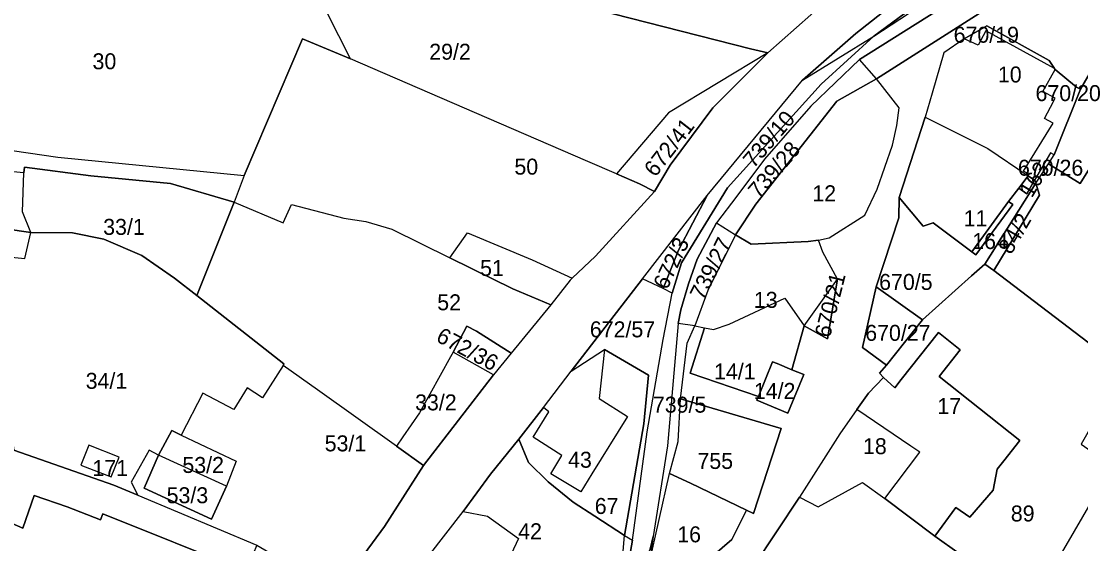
# Model space of a CAD drawing. Extents: x -629983 to -626385, y -1072828 to -1067897.
# Drawn here: x -627471.3 to -627272.2, y -1070358.3 to -1070260.1 of the extents above; entities that cross this region are included whole.
import ezdxf

# ---------------------------------------------------------------- set-up
doc = ezdxf.new("R2010")
doc.units = 0
doc.layers.add('Parcela nároku', color=7, linetype='Continuous')
doc.layers.add('Parcelní číslo', color=7, linetype='Continuous')

msp = doc.modelspace()

# ---------------------------------------------------------------- linework, layer by layer
at = {"layer": 'Parcela nároku'}
for points in [[(-627274.33, -1070229.94), (-627293.26, -1070245.57), (-627314.49, -1070262.38), (-627324.47, -1070271.16), (-627311.08, -1070262.87), (-627302.99, -1070256.91), (-627285.94, -1070243.76), (-627262.58, -1070228.21), (-627241.08, -1070214.74), (-627233.73, -1070210.98), (-627219.25, -1070207.1), (-627223.95, -1070202.72), (-627229.52, -1070202.24), (-627256.58, -1070217.73)], [(-627281.4, -1070246.83), (-627235.72, -1070217.21), (-627221.49, -1070213.01), (-627179.8, -1070206.02), (-627218.8, -1070213.83), (-627232.77, -1070222.84), (-627237.4, -1070226.24), (-627249.09, -1070231.35), (-627251.32, -1070233.14), (-627310.6, -1070270.86), (-627313.75, -1070267.23)], [(-627285.94, -1070243.76), (-627302.99, -1070256.91), (-627311.08, -1070262.87), (-627283.38, -1070244.72), (-627253.74, -1070227.22), (-627230.57, -1070214.05), (-627219.25, -1070207.1), (-627233.73, -1070210.98), (-627241.08, -1070214.74), (-627262.58, -1070228.21)], [(-627369.9, -1070256.15), (-627334.23, -1070265.22), (-627330.99, -1070266.01), (-627349.67, -1070277.25), (-627359.4, -1070288.74), (-627364.81, -1070286.4), (-627383.81, -1070278.2), (-627409.42, -1070267.15), (-627420.23, -1070245.71), (-627451.48, -1070240.87), (-627477.24, -1070236.31), (-627454.65, -1070210.58), (-627405.34, -1070220.98), (-627383.62, -1070245.45), (-627385.11, -1070252.28), (-627374.12, -1070255.08)], [(-627327.06, -1070239.59), (-627318.56, -1070244.65), (-627312.14, -1070249.25), (-627330.99, -1070266.01), (-627334.23, -1070265.22), (-627369.9, -1070256.15), (-627374.12, -1070255.08), (-627385.11, -1070252.28), (-627383.62, -1070245.45), (-627405.34, -1070220.98), (-627389.65, -1070224.29), (-627369.93, -1070230.55), (-627368.92, -1070227.99), (-627367.23, -1070223.22), (-627357.1, -1070227.42)], [(-627477.24, -1070236.31), (-627484.54, -1070251.9), (-627500.04, -1070281.83), (-627475.57, -1070284), (-627464.35, -1070285.62), (-627429.37, -1070289.04), (-627418.41, -1070263.38), (-627409.42, -1070267.15), (-627420.23, -1070245.71), (-627451.48, -1070240.87)], [(-627294.09, -1070263.34), (-627289.87, -1070260.94), (-627278.17, -1070267.43), (-627277.17, -1070268.92), (-627290.07, -1070261.89), (-627291.5, -1070264.57)], [(-627245.28, -1070273.22), (-627237.36, -1070278.17), (-627245.44, -1070292.1), (-627254.18, -1070287.03), (-627269.14, -1070285.43), (-627272.3, -1070290.53), (-627278.26, -1070286.84), (-627277.22, -1070285.2), (-627272.23, -1070272.86), (-627269.77, -1070268.48), (-627265.69, -1070260.15), (-627259.39, -1070263.83), (-627249.14, -1070270.65)], [(-627359.4, -1070288.74), (-627364.81, -1070286.4), (-627383.81, -1070278.2), (-627409.42, -1070267.15), (-627418.41, -1070263.38), (-627429.37, -1070289.04), (-627431.24, -1070294.08), (-627422.01, -1070297.98), (-627420.45, -1070294.52), (-627410.65, -1070297.05), (-627406.5, -1070297.67), (-627401.6, -1070299.12), (-627390.72, -1070304.51), (-627387.4, -1070299.82), (-627375.27, -1070304.93), (-627367.77, -1070308.37), (-627363.34, -1070304.23), (-627352.3, -1070292.06), (-627355.08, -1070290.6)], [(-627342.39, -1070292.8), (-627324.47, -1070271.16), (-627311.08, -1070262.87), (-627321, -1070271.87), (-627338.56, -1070291.39), (-627347.24, -1070305.44), (-627348.95, -1070311.14), (-627350.65, -1070310.32), (-627347.8, -1070303.06)], [(-627277.01, -1070274.54), (-627279.33, -1070273.25), (-627277.04, -1070269.12), (-627277.17, -1070268.92), (-627290.07, -1070261.89), (-627291.5, -1070264.57), (-627294.09, -1070263.34), (-627297.92, -1070265.98), (-627300.1, -1070273.55), (-627301.44, -1070278.09), (-627289.65, -1070284), (-627282.12, -1070289.1), (-627281.95, -1070288.79), (-627282.97, -1070288.21), (-627277.42, -1070279.24), (-627279.02, -1070278.33), (-627277.35, -1070275.17)], [(-627330.99, -1070266.01), (-627349.67, -1070277.25), (-627359.4, -1070288.74), (-627355.08, -1070290.6), (-627352.3, -1070292.06), (-627349.34, -1070287.13), (-627341.32, -1070276.32)], [(-627336.83, -1070292.94), (-627340.61, -1070297.95), (-627337.09, -1070300.21), (-627333.27, -1070294.46), (-627318.04, -1070275.09), (-627310.6, -1070270.86), (-627313.75, -1070267.23), (-627322.9, -1070276), (-627331.6, -1070286)], [(-627279.33, -1070273.25), (-627277.04, -1070269.12), (-627273, -1070272.48), (-627272.23, -1070272.86), (-627277.22, -1070285.2), (-627277.92, -1070284.77), (-627280.9, -1070289.93), (-627282.12, -1070289.1), (-627281.95, -1070288.79), (-627282.97, -1070288.21), (-627277.42, -1070279.24), (-627279.02, -1070278.33), (-627277.35, -1070275.17), (-627277.01, -1070274.54)], [(-627333.27, -1070294.46), (-627337.09, -1070300.21), (-627334.11, -1070301.99), (-627323.44, -1070301.49), (-627321.48, -1070301.2), (-627319.48, -1070300.75), (-627312.8, -1070296.52), (-627310.43, -1070291.6), (-627307.55, -1070283.36), (-627306.75, -1070279.66), (-627306.34, -1070276.31), (-627310.6, -1070270.86), (-627318.04, -1070275.09)], [(-627289.65, -1070284), (-627282.12, -1070289.1), (-627283.87, -1070291.42), (-627285.76, -1070293.94), (-627292.7, -1070303.39), (-627299.96, -1070297.97), (-627301.82, -1070298.6), (-627306.32, -1070293.18), (-627301.44, -1070278.09)], [(-627464.35, -1070285.62), (-627429.37, -1070289.04), (-627431.24, -1070294.08), (-627443.18, -1070290.54), (-627458.17, -1070289.11), (-627470.63, -1070287.47), (-627470.75, -1070288.53), (-627501.98, -1070285.58), (-627500.04, -1070281.83), (-627475.57, -1070284)], [(-627277.22, -1070285.2), (-627277.92, -1070284.77), (-627280.9, -1070289.93), (-627280.73, -1070290.16), (-627280.63, -1070290.51), (-627278.26, -1070286.84)], [(-627479.02, -1070297.25), (-627479.04, -1070298.42), (-627469.42, -1070299.74), (-627471.01, -1070295.88), (-627470.75, -1070288.53), (-627501.98, -1070285.58), (-627506.48, -1070294.32), (-627490.24, -1070295.72)], [(-627269.14, -1070285.43), (-627254.18, -1070287.03), (-627245.44, -1070292.1), (-627266.97, -1070320.91), (-627268.23, -1070322.38), (-627288.54, -1070306.92), (-627279.99, -1070292.78), (-627280.63, -1070290.51), (-627278.26, -1070286.84), (-627272.3, -1070290.53)], [(-627458.17, -1070289.11), (-627443.18, -1070290.54), (-627431.24, -1070294.08), (-627438.26, -1070311.63), (-627442.44, -1070308.35), (-627448.6, -1070304.07), (-627455.76, -1070301), (-627461.62, -1070299.82), (-627469.42, -1070299.74), (-627471.01, -1070295.88), (-627470.75, -1070288.53), (-627470.63, -1070287.47)], [(-627282.12, -1070289.1), (-627280.9, -1070289.93), (-627282.36, -1070292.48), (-627283.87, -1070291.42)], [(-627301.82, -1070298.6), (-627299.96, -1070297.97), (-627292.7, -1070303.39), (-627291.94, -1070303.96), (-627284.99, -1070294.5), (-627285.76, -1070293.94), (-627283.87, -1070291.42), (-627282.36, -1070292.48), (-627280.9, -1070289.93), (-627280.73, -1070290.16), (-627280.63, -1070290.51), (-627290.23, -1070305.72), (-627292.73, -1070307.89), (-627301.97, -1070316.17), (-627310.63, -1070309.97), (-627306.4, -1070297.04), (-627306.32, -1070293.18)], [(-627280.63, -1070290.51), (-627279.99, -1070292.78), (-627288.54, -1070306.92), (-627290.23, -1070305.72)], [(-627354.53, -1070308.48), (-627342.39, -1070292.8), (-627347.8, -1070303.06), (-627350.65, -1070310.32)], [(-627378.87, -1070310.38), (-627371.73, -1070313.39), (-627379.18, -1070322.46), (-627385.75, -1070318.34), (-627387.51, -1070317.39), (-627390.09, -1070322.26), (-627390.58, -1070323.13), (-627396.45, -1070333.65), (-627399.58, -1070338.17), (-627400.78, -1070339.91), (-627415.62, -1070329.36), (-627422.06, -1070324.78), (-627421.91, -1070324.46), (-627438.26, -1070311.63), (-627431.24, -1070294.08), (-627422.01, -1070297.98), (-627420.45, -1070294.52), (-627410.65, -1070297.05), (-627406.5, -1070297.67), (-627401.6, -1070299.12), (-627390.72, -1070304.51)], [(-627285.76, -1070293.94), (-627284.99, -1070294.5), (-627291.94, -1070303.96), (-627292.7, -1070303.39)], [(-627469.42, -1070299.74), (-627479.04, -1070298.42), (-627493.23, -1070296.53), (-627507.13, -1070295.59), (-627509.97, -1070301.16), (-627510.28, -1070301.76), (-627502.57, -1070305.47), (-627493.05, -1070303.61), (-627489.75, -1070302.95), (-627478.71, -1070303.86), (-627478.14, -1070303.92), (-627470.55, -1070304.67)], [(-627340.61, -1070297.95), (-627337.09, -1070300.21), (-627342.27, -1070310.69), (-627344.74, -1070317.31), (-627347.86, -1070316.85), (-627347.33, -1070314.29), (-627345.92, -1070309.44), (-627344.25, -1070304.76)], [(-627461.62, -1070299.82), (-627455.76, -1070301), (-627448.6, -1070304.07), (-627442.44, -1070308.35), (-627438.26, -1070311.63), (-627421.91, -1070324.46), (-627422.06, -1070324.78), (-627425.91, -1070330.87), (-627428.78, -1070328.99), (-627431.33, -1070333.05), (-627437.16, -1070329.94), (-627441.2, -1070337.83), (-627442.96, -1070336.99), (-627445.44, -1070341.59), (-627447.23, -1070340.65), (-627450.6, -1070346.67), (-627449.35, -1070349.16), (-627453.84, -1070347.28), (-627472.61, -1070340.67), (-627478.14, -1070303.92), (-627470.55, -1070304.67), (-627469.42, -1070299.74)], [(-627375.27, -1070304.93), (-627367.77, -1070308.37), (-627368.12, -1070308.7), (-627371.73, -1070313.39), (-627378.87, -1070310.38), (-627390.72, -1070304.51), (-627387.4, -1070299.82)], [(-627337.09, -1070300.21), (-627342.27, -1070310.69), (-627344.74, -1070317.31), (-627342.9, -1070317.68), (-627341.18, -1070317.97), (-627338.28, -1070317.01), (-627327.83, -1070312.1), (-627324.2, -1070317.33), (-627317.89, -1070308.52), (-627320.64, -1070303.47), (-627321.48, -1070301.2), (-627323.44, -1070301.49), (-627334.11, -1070301.99)], [(-627478.14, -1070303.92), (-627472.61, -1070340.67), (-627453.84, -1070347.28), (-627449.35, -1070349.16), (-627426.96, -1070358.52), (-627429.07, -1070363.41), (-627455.93, -1070352.67), (-627456.37, -1070353.79), (-627462.61, -1070351.34), (-627468.81, -1070349.21), (-627470.94, -1070355.34), (-627478.59, -1070352.03), (-627499.33, -1070342.21), (-627492.09, -1070303.67), (-627478.71, -1070304.58), (-627478.71, -1070303.86)], [(-627348.95, -1070311.14), (-627350.65, -1070310.32), (-627354.53, -1070308.48), (-627367.96, -1070325.83), (-627361.7, -1070321.78), (-627353.44, -1070326.59), (-627354.29, -1070335.76), (-627357.89, -1070356.74), (-627356.41, -1070357.6), (-627353.65, -1070337.23), (-627350.65, -1070319.87)], [(-627324.2, -1070317.33), (-627317.89, -1070308.52), (-627319.78, -1070319.75)], [(-627313.2, -1070321.39), (-627310.63, -1070309.97), (-627301.97, -1070316.17), (-627308.72, -1070324.72)], [(-627338.28, -1070317.01), (-627327.83, -1070312.1), (-627324.2, -1070317.33), (-627326.48, -1070325.55), (-627329.26, -1070324.4), (-627330.11, -1070324.05), (-627332.78, -1070330.59), (-627345.58, -1070326.23), (-627342.9, -1070317.68), (-627341.18, -1070317.97)], [(-627347.86, -1070316.85), (-627349.85, -1070339.86), (-627352.52, -1070356.91), (-627353.37, -1070362.37), (-627349.44, -1070345.07), (-627347.83, -1070339.08), (-627347.37, -1070331.02), (-627346.17, -1070320.59), (-627344.74, -1070317.31)], [(-627385.75, -1070318.34), (-627379.18, -1070322.46), (-627382.5, -1070326.5), (-627390.09, -1070322.26), (-627387.51, -1070317.39)], [(-627305.92, -1070327.38), (-627298.95, -1070318.59), (-627294.84, -1070321.85), (-627298.81, -1070326.86), (-627283.65, -1070338.87), (-627286.65, -1070342.66), (-627287.89, -1070344.23), (-627288.67, -1070348.17), (-627293.06, -1070353.29), (-627295.67, -1070351.47), (-627299.63, -1070356.83), (-627309, -1070349.79), (-627302.45, -1070341.03), (-627304.11, -1070339.91), (-627314.26, -1070333.05), (-627312.06, -1070329.96), (-627309.24, -1070327.02), (-627307.16, -1070328.95)], [(-627396.45, -1070333.65), (-627399.58, -1070338.17), (-627400.78, -1070339.91), (-627395.65, -1070343.56), (-627382.5, -1070326.5), (-627390.09, -1070322.26), (-627390.58, -1070323.13)], [(-627366.14, -1070348.54), (-627371.76, -1070345.13), (-627369.68, -1070341.71), (-627375.1, -1070338.24), (-627372.12, -1070333.46), (-627373.15, -1070332.69), (-627377.74, -1070338.6), (-627375.93, -1070342.99), (-627372.27, -1070346.61), (-627367.57, -1070350.45), (-627363.48, -1070353.1), (-627357.89, -1070356.74), (-627354.29, -1070335.76), (-627353.44, -1070326.59), (-627361.7, -1070321.78), (-627362.69, -1070330.98), (-627357.36, -1070334.37), (-627364.06, -1070345.12)], [(-627375.1, -1070338.24), (-627372.12, -1070333.46), (-627373.15, -1070332.69), (-627367.96, -1070325.83), (-627361.7, -1070321.78), (-627362.69, -1070330.98), (-627357.36, -1070334.37), (-627364.06, -1070345.12), (-627366.14, -1070348.54), (-627371.76, -1070345.13), (-627369.68, -1070341.71)], [(-627445.44, -1070341.59), (-627447.23, -1070340.65), (-627450.6, -1070346.67), (-627449.35, -1070349.16), (-627426.96, -1070358.52), (-627419.94, -1070362.66), (-627411.51, -1070366.62), (-627403.01, -1070355.05), (-627395.65, -1070343.56), (-627400.78, -1070339.91), (-627415.62, -1070329.36), (-627422.06, -1070324.78), (-627425.91, -1070330.87), (-627428.78, -1070328.99), (-627431.33, -1070333.05), (-627437.16, -1070329.94), (-627441.2, -1070337.83), (-627430.9, -1070342.76), (-627432.7, -1070347.45), (-627435.51, -1070353.65), (-627448.18, -1070347.83)], [(-627326.48, -1070325.55), (-627324.25, -1070326.47), (-627326.78, -1070332.63), (-627327.22, -1070333.7), (-627333.08, -1070331.31), (-627332.78, -1070330.59), (-627330.11, -1070324.05), (-627329.26, -1070324.4)], [(-627266.34, -1070343.62), (-627279.05, -1070365.5), (-627273.58, -1070370.07), (-627255.6, -1070379.2), (-627241.89, -1070342.47), (-627265.18, -1070327.36), (-627272.15, -1070339.58)], [(-627347.83, -1070339.08), (-627347.37, -1070331.02), (-627328.48, -1070336.63), (-627333.69, -1070352.58), (-627335, -1070351.94), (-627345.53, -1070346.88), (-627349.44, -1070345.07)], [(-627302.45, -1070341.03), (-627304.11, -1070339.91), (-627314.26, -1070333.05), (-627317.5, -1070337.6), (-627325.04, -1070349.5), (-627321.55, -1070351.31), (-627313.23, -1070346.77), (-627309, -1070349.79)], [(-627441.2, -1070337.83), (-627430.9, -1070342.76), (-627432.7, -1070347.45), (-627445.44, -1070341.59), (-627442.96, -1070336.99)], [(-627377.74, -1070338.6), (-627383.11, -1070345.19), (-627388.2, -1070352.2), (-627383.65, -1070353.11), (-627377.82, -1070357.3), (-627379.2, -1070360.24), (-627363.18, -1070370.8), (-627358.2, -1070359.64), (-627357.89, -1070356.74), (-627363.48, -1070353.1), (-627367.57, -1070350.45), (-627372.27, -1070346.61), (-627375.93, -1070342.99)], [(-627454.34, -1070345.72), (-627452.86, -1070342), (-627458.56, -1070339.76), (-627460.06, -1070343.52)], [(-627452.86, -1070342), (-627458.56, -1070339.76), (-627460.06, -1070343.52), (-627454.34, -1070345.72)], [(-627432.7, -1070347.45), (-627445.44, -1070341.59), (-627448.18, -1070347.83), (-627435.51, -1070353.65)], [(-627349.44, -1070345.07), (-627345.53, -1070346.88), (-627335, -1070351.94), (-627337.74, -1070357.49), (-627342.79, -1070361.77), (-627347.04, -1070363.86), (-627351.19, -1070371.75), (-627355.23, -1070370.19), (-627353.37, -1070362.37)], [(-627325.04, -1070349.5), (-627321.55, -1070351.31), (-627313.23, -1070346.77), (-627309, -1070349.79), (-627299.63, -1070356.83), (-627290.51, -1070363.35), (-627293.97, -1070365.98), (-627302.71, -1070372.61), (-627314.46, -1070387.99), (-627324.67, -1070379.13), (-627322.79, -1070376.17), (-627318.23, -1070379.43), (-627312.01, -1070370.72), (-627325.89, -1070360.8), (-627329.32, -1070365.6), (-627333.66, -1070362.54)], [(-627477.66, -1070367.54), (-627477.14, -1070361.52), (-627478.59, -1070352.03), (-627470.94, -1070355.34), (-627468.81, -1070349.21), (-627462.61, -1070351.34), (-627456.37, -1070353.79), (-627455.93, -1070352.67), (-627429.07, -1070363.41), (-627426.11, -1070364.59), (-627430.93, -1070374.9), (-627424.08, -1070376.75), (-627419.9, -1070377.83), (-627432.7, -1070392.58), (-627429.59, -1070386.99), (-627427.82, -1070383.61), (-627428.34, -1070382.69), (-627459.6, -1070371.3), (-627474.17, -1070367.79)], [(-627394.72, -1070360.62), (-627388.2, -1070352.2), (-627383.65, -1070353.11), (-627377.82, -1070357.3), (-627379.2, -1070360.24), (-627385.55, -1070374.72), (-627392.6, -1070388.53), (-627393.1, -1070389.31), (-627397.14, -1070386.81), (-627384.73, -1070366.74), (-627391.26, -1070362.69)], [(-627358.2, -1070359.64), (-627357.89, -1070356.74), (-627356.41, -1070357.6), (-627358.49, -1070369.37), (-627359.89, -1070373.11), (-627363.18, -1070370.8)], [(-627353.12, -1070359.27), (-627352.52, -1070356.91), (-627353.37, -1070362.37), (-627355.23, -1070370.19), (-627357.77, -1070369.67)]]:
    msp.add_lwpolyline(points, close=True, dxfattribs=at)
for points in [[(-627342.79, -1070361.77), (-627337.74, -1070357.49), (-627335, -1070351.94), (-627333.69, -1070352.58), (-627328.48, -1070336.63), (-627347.37, -1070331.02), (-627346.17, -1070320.59), (-627344.74, -1070317.31), (-627342.9, -1070317.68), (-627345.58, -1070326.23), (-627332.78, -1070330.59), (-627333.08, -1070331.31), (-627327.22, -1070333.7), (-627326.78, -1070332.63), (-627324.25, -1070326.47), (-627326.48, -1070325.55), (-627324.2, -1070317.33), (-627319.78, -1070319.75), (-627317.89, -1070308.52), (-627320.64, -1070303.47), (-627321.48, -1070301.2), (-627319.48, -1070300.75), (-627312.8, -1070296.52), (-627310.43, -1070291.6), (-627307.55, -1070283.36), (-627306.75, -1070279.66), (-627306.34, -1070276.31), (-627310.6, -1070270.86), (-627251.32, -1070233.14)], [(-627505.98, -1070464.68), (-627477.81, -1070449.31), (-627458.09, -1070435.4), (-627450.22, -1070429.04), (-627437.75, -1070413.5), (-627426.3, -1070400.46), (-627415.46, -1070387.81), (-627412.15, -1070383.27), (-627394.72, -1070360.62), (-627388.2, -1070352.2), (-627383.11, -1070345.19), (-627377.74, -1070338.6), (-627373.15, -1070332.69), (-627367.96, -1070325.83), (-627354.53, -1070308.48), (-627342.39, -1070292.8), (-627324.47, -1070271.16), (-627314.49, -1070262.38), (-627293.26, -1070245.57)], [(-627358.49, -1070369.37), (-627356.41, -1070357.6), (-627353.65, -1070337.23), (-627350.65, -1070319.87), (-627348.95, -1070311.14), (-627347.24, -1070305.44), (-627338.56, -1070291.39), (-627321, -1070271.87), (-627311.08, -1070262.87), (-627283.38, -1070244.72)], [(-627281.4, -1070246.83), (-627313.75, -1070267.23), (-627322.9, -1070276), (-627331.6, -1070286), (-627336.83, -1070292.94), (-627340.61, -1070297.95), (-627344.25, -1070304.76), (-627345.92, -1070309.44), (-627347.33, -1070314.29), (-627347.86, -1070316.85), (-627349.85, -1070339.86), (-627352.52, -1070356.91), (-627353.12, -1070359.27)], [(-627312.14, -1070249.25), (-627330.99, -1070266.01), (-627341.32, -1070276.32), (-627349.34, -1070287.13), (-627352.3, -1070292.06), (-627363.34, -1070304.23), (-627367.77, -1070308.37), (-627368.12, -1070308.7), (-627371.73, -1070313.39), (-627379.18, -1070322.46), (-627382.5, -1070326.5), (-627395.65, -1070343.56), (-627403.01, -1070355.05), (-627411.51, -1070366.62), (-627414.33, -1070370.56), (-627419.9, -1070377.83), (-627432.7, -1070392.58), (-627443.88, -1070409.16), (-627459.21, -1070426.46), (-627472.89, -1070436.01), (-627478.35, -1070438.88), (-627495.48, -1070449.89), (-627510.48, -1070456.69), (-627527.27, -1070465.04)], [(-627269.77, -1070268.48), (-627272.23, -1070272.86), (-627273, -1070272.48), (-627277.04, -1070269.12), (-627277.17, -1070268.92), (-627278.17, -1070267.43), (-627289.87, -1070260.94), (-627294.09, -1070263.34), (-627297.92, -1070265.98), (-627300.1, -1070273.55), (-627301.44, -1070278.09), (-627306.32, -1070293.18), (-627306.4, -1070297.04), (-627310.63, -1070309.97), (-627313.2, -1070321.39), (-627308.72, -1070324.72), (-627310.01, -1070326.19), (-627309.24, -1070327.02), (-627312.06, -1070329.96), (-627314.26, -1070333.05), (-627317.5, -1070337.6), (-627325.04, -1070349.5), (-627333.66, -1070362.54)], [(-627266.34, -1070343.62), (-627279.05, -1070365.5), (-627281.46, -1070369.18), (-627290.51, -1070363.35), (-627299.63, -1070356.83), (-627295.67, -1070351.47), (-627293.06, -1070353.29), (-627288.67, -1070348.17), (-627287.89, -1070344.23), (-627286.65, -1070342.66), (-627283.65, -1070338.87), (-627298.81, -1070326.86), (-627294.84, -1070321.85), (-627298.95, -1070318.59), (-627305.92, -1070327.38), (-627307.16, -1070328.95), (-627309.24, -1070327.02), (-627310.01, -1070326.19), (-627308.72, -1070324.72), (-627301.97, -1070316.17), (-627292.73, -1070307.89), (-627290.23, -1070305.72), (-627288.54, -1070306.92), (-627268.23, -1070322.38)]]:
    msp.add_lwpolyline(points, dxfattribs=at)

# ---------------------------------------------------------------- texts
at = {"layer": 'Parcelní číslo'}
for s, p in [('670/19', (-627296.09, -1070264.1)), ('29/2', (-627394.6, -1070267.29)), ('30', (-627457.85, -1070269.09)), ('10', (-627287.78, -1070271.57)), ('670/20', (-627280.71, -1070275.07)), ('50', (-627378.6, -1070288.89)), ('670/26', (-627284.01, -1070289.09)), ('12', (-627322.63, -1070293.9)), ('33/1', (-627455.85, -1070300.21)), ('11', (-627294.22, -1070298.6)), ('164', (-627292.6, -1070302.88)), ('51', (-627385.05, -1070307.94)), ('670/5', (-627310.09, -1070310.56)), ('13', (-627333.62, -1070313.93)), ('52', (-627393.1, -1070314.39)), ('672/57', (-627364.43, -1070319.47)), ('670/27', (-627312.7, -1070320.13)), ('14/1', (-627341.1, -1070327.39)), ('34/1', (-627459.14, -1070329.15)), ('14/2', (-627333.62, -1070331.05)), ('33/2', (-627397.26, -1070333.2)), ('739/5', (-627352.59, -1070333.63)), ('17', (-627299.15, -1070333.89)), ('53/1', (-627414.24, -1070340.9)), ('18', (-627313.12, -1070341.43)), ('43', (-627368.52, -1070343.98)), ('171', (-627457.87, -1070345.53)), ('53/2', (-627440.97, -1070344.96)), ('755', (-627344.22, -1070344.21)), ('53/3', (-627443.93, -1070350.65)), ('67', (-627363.51, -1070352.67)), ('89', (-627285.35, -1070354.08)), ('42', (-627377.89, -1070357.42)), ('16', (-627348.01, -1070358))]:
    msp.add_text(s, height=3, dxfattribs=at).set_placement(p)
for s, rotation, p in [('739/10', 49.3778, (-627333.66, -1070287.84)), ('672/41', 52.204, (-627352.12, -1070289.51)), ('739/28', 49.1051, (-627332.72, -1070293.57)), ('163', 59.0323, (-627281.4, -1070293.4)), ('84/2', 59.809, (-627285.3, -1070304.07)), ('672/3', 64.8474, (-627349.94, -1070310.71)), ('739/27', 63.435, (-627343.13, -1070312.69)), ('670/21', 75.9619, (-627319.33, -1070319.69)), ('672/36', 331.848, (-627393.52, -1070320.11))]:
    msp.add_text(s, height=3, rotation=rotation, dxfattribs=at).set_placement(p)

doc.saveas('drawing.dxf')
